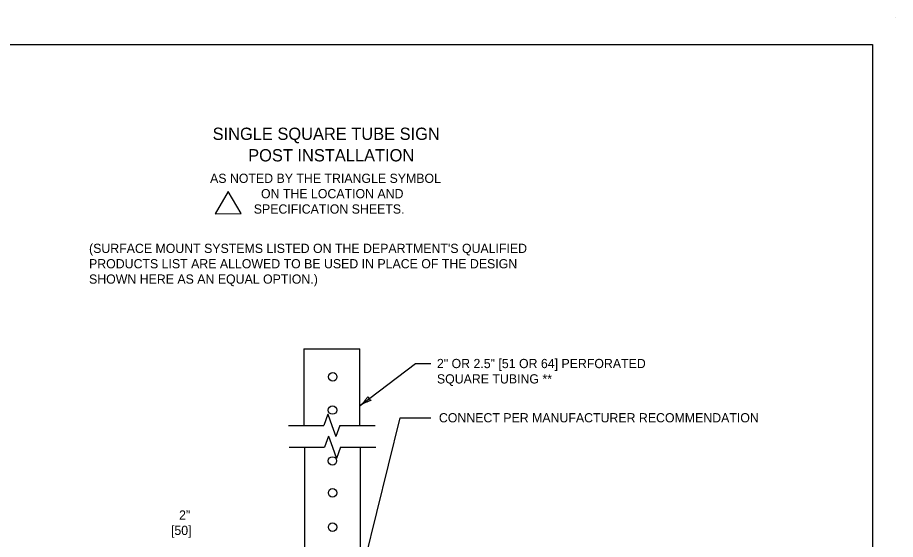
# Model space of a CAD drawing. Extents: x 49940 to 50043, y 49986 to 50011.
# Drawn here: x 50011.19 to 50016.9, y 49995.78 to 49999.18 of the extents above; entities that cross this region are included whole.
import ezdxf

# ---------------------------------------------------------------- set-up
doc = ezdxf.new("R2010")
doc.units = 0
for name, color, linetype in [('Level 1', 7, 'Continuous'), ('Level 2', 7, 'Continuous'), ('Level 3', 7, 'Continuous'), ('Level 6', 7, 'Continuous')]:
    doc.layers.add(name, color=color, linetype=linetype)

msp = doc.modelspace()

# ---------------------------------------------------------------- linework, layer by layer
at = {"layer": 'Level 1'}
for p, q in [((50016.9001, 49999.1756), (50016.9001, 49999.1756)), ((50013.0499, 49997.0187), (50013.4133, 49997.0187))]:
    msp.add_line(p, q, dxfattribs=at)
msp.add_lwpolyline([(49999.3835, 49998.9992), (50016.7501, 49998.9992), (50016.7501, 49987.7988), (49999.3835, 49987.7988)], close=True, dxfattribs=at)
for points in [[(50013.0499, 49997.0187), (50013.0499, 49996.5197)], [(50013.4133, 49996.5197), (50013.4133, 49997.0187)], [(50013.0548, 49996.3776), (50013.0548, 49995.493), (50013.4182, 49995.493), (50013.418, 49996.3777)]]:
    msp.add_lwpolyline(points, dxfattribs=at)
for centre in [(50013.2377, 49996.8366), (50013.2364, 49996.6199), (50013.2355, 49996.2882), (50013.2371, 49996.0806), (50013.2371, 49995.8575)]:
    msp.add_circle(centre, 0.0277, dxfattribs=at)
at = {"layer": 'Level 2'}
msp.add_lwpolyline([(50012.4733, 49997.8982), (50012.6411, 49997.8987), (50012.5567, 49998.0436)], close=True, dxfattribs=at)
at = {"layer": 'Level 3'}
for p, q in [((50013.4164, 49996.6488), (50013.7759, 49996.9228)), ((50013.7759, 49996.9228), (50013.876, 49996.9228)), ((50013.3963, 49995.426), (50013.6761, 49996.5696)), ((50013.6761, 49996.5696), (50013.876, 49996.5696))]:
    msp.add_line(p, q, dxfattribs=at)
for centre, radius, start, end in [((50013.2662, 49996.8269), 0.233, 310.1409, 329.3907), ((50013.5184, 49996.7265), 0.0548, 199.4524, 235.1747), ((50013.5438, 49996.4666), 0.2223, 104.7696, 124.9531)]:
    msp.add_arc(centre, radius, start, end, dxfattribs=at)
at = {"layer": 'Level 6'}
for p, q in [((50013.2057, 49996.5928), (50013.1798, 49996.5197)), ((50013.2057, 49996.5928), (50013.2316, 49996.5197)), ((50012.9499, 49996.5197), (50013.1798, 49996.5197)), ((50013.2316, 49996.5197), (50013.2575, 49996.4466)), ((50013.2834, 49996.5197), (50013.2575, 49996.4466)), ((50013.2834, 49996.5197), (50013.5133, 49996.5197)), ((50013.2105, 49996.4507), (50013.1846, 49996.3776)), ((50013.2105, 49996.4507), (50013.2364, 49996.3776)), ((50012.9548, 49996.3776), (50013.1846, 49996.3776)), ((50013.2364, 49996.3776), (50013.2623, 49996.3045)), ((50013.2882, 49996.3776), (50013.2623, 49996.3045)), ((50013.2882, 49996.3777), (50013.518, 49996.3777))]:
    msp.add_line(p, q, dxfattribs=at)

# ---------------------------------------------------------------- texts
at = {"layer": 'Level 2'}
for s, height, p in [('SINGLE SQUARE TUBE SIGN', 0.0799, (50012.4563, 49998.3788)), ('POST INSTALLATION', 0.0799, (50012.6877, 49998.2388)), ('AS NOTED BY THE TRIANGLE SYMBOL', 0.06, (50012.4397, 49998.0988)), ('ON THE LOCATION AND', 0.06, (50012.7711, 49997.9988)), ('SPECIFICATION SHEETS.', 0.06, (50012.724, 49997.8988)), ("(SURFACE MOUNT SYSTEMS LISTED ON THE DEPARTMENT'S QUALIFIED ", 0.06, (50011.652, 49997.6426)), ('PRODUCTS LIST ARE ALLOWED TO BE USED IN PLACE OF THE DESIGN ', 0.06, (50011.652, 49997.5426)), ('SHOWN HERE AS AN EQUAL OPTION.)', 0.06, (50011.652, 49997.4426)), ('2" OR 2.5" [51 OR 64] PERFORATED', 0.06, (50013.916, 49996.8928)), ('SQUARE TUBING **', 0.06, (50013.916, 49996.7928)), ('CONNECT PER MANUFACTURER RECOMMENDATION', 0.06, (50013.9291, 49996.5396)), ('2"', 0.06, (50012.238, 49995.9063)), ('[50]', 0.06, (50012.1851, 49995.8063))]:
    msp.add_text(s, height=height, dxfattribs=at).set_placement(p)

doc.saveas('drawing.dxf')
